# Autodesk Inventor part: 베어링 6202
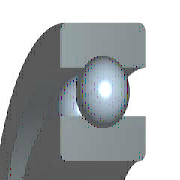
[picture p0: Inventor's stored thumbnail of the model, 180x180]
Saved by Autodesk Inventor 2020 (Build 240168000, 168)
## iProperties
Company: 한국ATC센터
IsCustomPart: 1
Created: 2015-12
Part Number: 베어링 6202
Material: 강철, 연강
Description: 깊은 그루브 볼 베어링
Document SubType Name: Modeling
Standard: KS B 2023
Designer: mdu
Standards Organization: KS
Language: ko-KR
Size Designation: 6202 - 15 x 35 x 11
Categories: <MemberInstance><Categories><Category DisplayName="샤프트 부품" InternalName="7f7aeb1f-a693-4053-b835-cee3144e0d98" Mnemonic="SHFT"><Category DisplayName="베어링" Inter
Density: 7.86 g/cm^3
Mass: 45.8724 g
Surface Area: 51.5584 cm^2
Volume: 5.83618 cm^3
Appearance: 보라색
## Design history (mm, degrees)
sketch "스케치" dims "d0" = 5.2 (= -0.26 x WD + 0.26 x BD)
  geometry: L1 (2.9, 12.5)-(8.1, 12.5); L2 (5.5, 12.5)-(5.5, 9.9); L3 (5.5, 12.5)-(5.5, 15.1); L4 (3.568, 10.76)-(0, 10.76); L5 (0, 7.5)-(11, 7.5); L6 (3.568, 14.24)-(0, 14.24); L7 (0, 17.5)-(11, 17.5); L8 (11, 7.5)-(11, 10.76); L9 (7.432, 10.76)-(11, 10.76); L10 (7.432, 14.24)-(11, 14.24); L11 (11, 17.5)-(11, 14.24); L12 (-1.4, 0)-(8.4, 0) reference; L13 (0, -0.3)-(0, 5.3) reference
  constraints: 22 end point, 4 point on line, 2 collinear, 2 perpendicular, 2 symmetric about line, 1 midpoint, 1 parallel, 14 other
  dimensions: "d9" = 15 diameter of L5 L12 (= WD); "d11" = 35 diameter of L7 L12 (= BD); "d12" = 11 distance between parallel lines of L8 L13 (= KB); "d13" = 21.52 diameter of L9 L12 (= 0.326 x BD + 0.674 x WD)
revolve "본체" stored, may be unused: angle "d6" = 90 deg
revolve "볼" stored, may be unused: angle "d7" = 90 deg
pattern_circular "IDS_ARRAYBALL[SIMPL:T]" dims angle "d3" = 360 deg
body "Solid1"
fillet "모깎기1" dims "d1" = 0.6 (= KRS)
other parameters: "WD" = 15 [user parameter; used in 5 equation terms], "BD" = 35 [user parameter; used in 5 equation terms], "KB" = 11 [user parameter; used in 1 equation term], "KRS" = 0.6 [user parameter; used in 1 equation term], "d4" = 0, "d5" = 0, "d8" = 0, "d14" = 0, "d15" = 0, "BBA" = 0 [user parameter], "BC0" = 3750000 [user parameter], "BC" = 7800000 [user parameter], "BR" = 17.5 (= 0.5 x BD) [user parameter], "WR" = 7.5 (= 0.5 x WD) [user parameter]
